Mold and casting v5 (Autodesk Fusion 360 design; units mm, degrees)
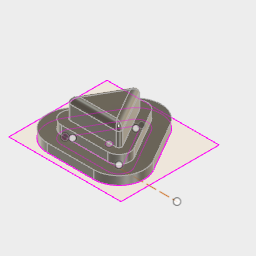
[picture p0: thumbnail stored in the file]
sketch "Sketch1"
  line L1 (18.2679, 0) -> (1.7321, 0)
  line L2 (10.866, 15.8205) -> (19.134, 1.5)
  line L3 (40, 0) -> (20, 0)
  line L4 (0.866, 1.5) -> (9.134, 15.8205)
  line L5 (18.2679, -3) -> (1.7321, -3)
  line L6 (13.4641, 17.3205) -> (21.7321, 3)
  line L7 (-1.7321, 3) -> (6.5359, 17.3205)
  line L8 (17.7942, 19.8205) -> (26.0622, 5.5)
  line L9 (-6.0622, 5.5) -> (2.2058, 19.8205)
  line L10 (18.2679, -8) -> (1.7321, -8)
  line L11 (30, 25) -> (-10, 25)
  line L12 (30, -10.0023) -> (30, 25)
  line L13 (-10, -10.0023) -> (30, -10.0023)
  line L14 (-10, 25) -> (-10, -10.0023)
  arc A1 centre (1.7321, 1) radius 1 clockwise from (1.7321, 0) to (0.866, 1.5)
  arc A2 centre (10, 15.3205) radius 1 clockwise from (9.134, 15.8205) to (10.866, 15.8205)
  arc A3 centre (18.2679, 1) radius 1 clockwise from (19.134, 1.5) to (18.2679, 0)
  circle C1 centre (10, 5.7735) radius 1
  arc A4 centre (18.2679, 1) radius 4 clockwise from (21.7321, 3) to (18.2679, -3)
  arc A5 centre (10, 15.3205) radius 4 clockwise from (6.5359, 17.3205) to (13.4641, 17.3205)
  arc A6 centre (1.7321, 1) radius 4 clockwise from (1.7321, -3) to (-1.7321, 3)
  arc A7 centre (10, 15.3205) radius 9 clockwise from (2.2058, 19.8205) to (17.7942, 19.8205)
  arc A8 centre (1.7321, 1) radius 9 clockwise from (1.7321, -8) to (-6.0622, 5.5)
  arc A9 centre (18.2679, 1) radius 9 clockwise from (26.0622, 5.5) to (18.2679, -8)
  point P2 (0, 0)
  point P3 (20, 0)
  point P4 (10, 17.3205)
  dimension "d1" distance P2 P3 = 20
  dimension "d2" angle L2 L3 = 120
  dimension "d3" distance P3 P4 = 20
  dimension "d4" radius A1 = 1
  dimension "d5" = 3
  dimension "d11" diameter C1 = 2
  dimension "d18" = 8
extrude "Extrude1" sketch "Sketch1" profile of L1 L2 L4 A1 A2 A3 A5 L5 A6 A4 L7 L6 blind 5
extrude "Extrude2" sketch "Sketch1" profile of L1 L2 L4 A1 A2 A3 blind 10
fillet "Fillet1" radius 2
extrude "Extrude3" new body sketch "Sketch1" profile of C1 blind 5
extrude "Extrude4" sketch "Sketch1" profile of C1 blind 5
extrude "Extrude5" of existing geometry blind -2
extrude "Extrude6" sketch "Sketch1" profile of A5 L5 A6 A4 L7 L6 A8 L8 A7 A9 L9 L10 blind 2
move "Move1"
extrude "Extrude7" add of existing geometry blind 1
sketch "Sketch2" plane through (0, 0, 13) normal (0, 0, 1) x axis (-1, 0, 0)
  line L1 (-3.4641, -2) -> (-10, -13.3205)
  line L2 (-16.5359, -2) -> (-3.4641, -2)
  line L3 (-10, -13.3205) -> (-16.5359, -2)
  line L4 (12, -27) -> (-32, -27)
  line L5 (12, 9) -> (12, -27)
  line L6 (-32, 9) -> (12, 9)
  line L7 (-32, -27) -> (-32, 9)
  line L8 (12, 9) -> (-32, -27)
  line L9 (-32, 9) -> (12, -27)
extrude "Extrude10" sketch "Sketch1" profile of L1 L2 L4 A1 A2 A3 A5 L5 A6 A4 L7 L6 C1 A8 L8 A7 A9 L9 L10 L11 L12 L13 L14 blind -5
move "Move3" TranslateX 0 TranslateY 0 TranslateZ 18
